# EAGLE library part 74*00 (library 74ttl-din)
Quad 2-input NAND gate
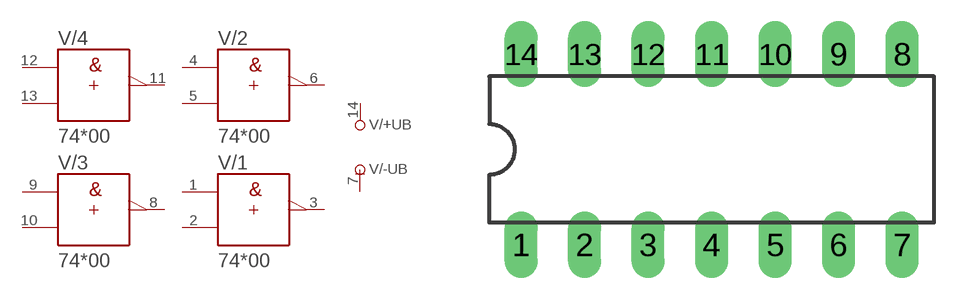
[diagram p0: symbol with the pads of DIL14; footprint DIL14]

Designator prefix V; gates /+UB=+UB /-UB=-UB /1=00 /2=00 /3=00 /4=00

## 7400N, 74HC00N, 74HCT00N, 74LS00N  [DIL14]
1  /1:A  in
2  /1:B  in
3  /1:Y  out
4  /2:A  in
5  /2:B  in
6  /2:Y  out
7  /-UB:-UB  pwr
8  /3:Y  out
9  /3:A  in
10  /3:B  in
11  /4:Y  out
12  /4:A  in
13  /4:B  in
14  /+UB:+UB  pwr

## Footprint DIL14 (pad centres in mm)
Dual In Line Package
drill 0.813 long: 1 -7.62,-3.81; 2 -5.08,-3.81; 3 -2.54,-3.81; 4 0,-3.81; 5 2.54,-3.81; 6 5.08,-3.81; 7 7.62,-3.81; 8 7.62,3.81; 9 5.08,3.81; 10 2.54,3.81; 11 0,3.81; 12 -2.54,3.81; 13 -5.08,3.81; 14 -7.62,3.81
